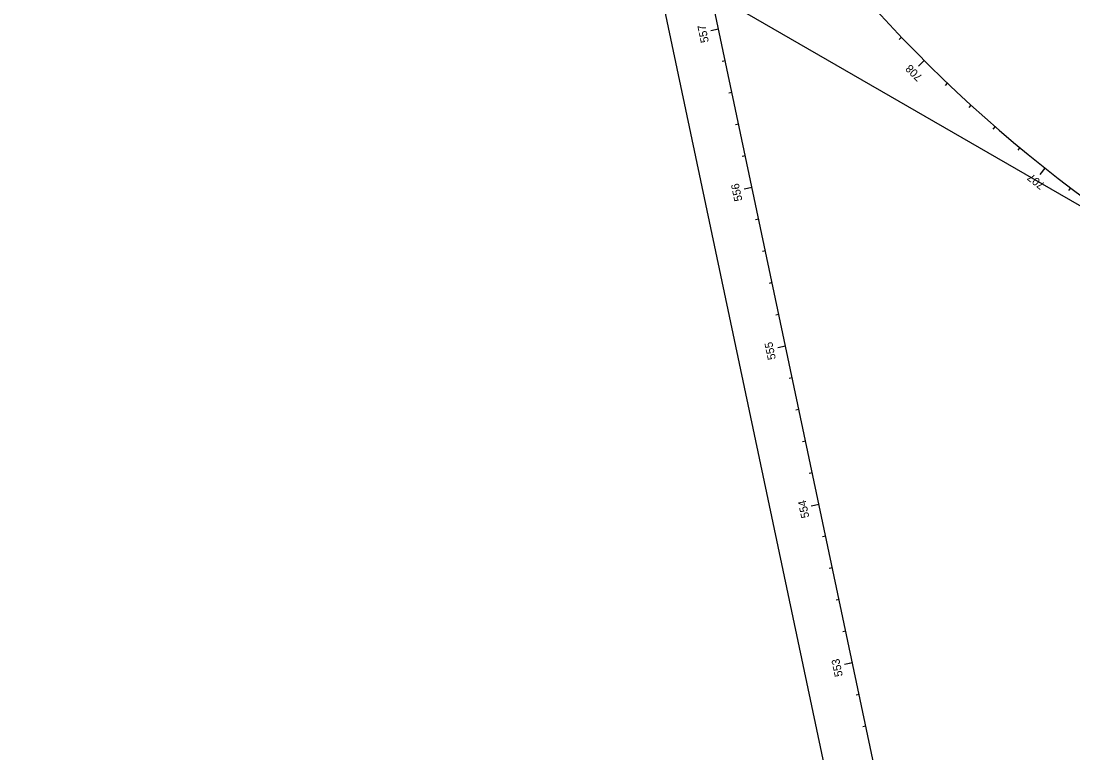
# Model space of a CAD drawing. Extents: x 2003883 to 2007688, y 399149 to 412300.
# Drawn here: x 2005600 to 2006250, y 402640 to 403092 of the extents above; entities that cross this region are included whole.
import ezdxf

# ---------------------------------------------------------------- set-up
doc = ezdxf.new("R2010")
doc.units = 0
for name, color, linetype in [('BaselineSurvey', 7, 'Continuous'), ('CLConst_dp', 7, 'Continuous'), ('ConstLines', 7, 'Continuous'), ('Default', 7, 'Continuous'), ('TextAlgnStation100', 7, 'Continuous'), ('TextAlgnStation500', 7, 'Continuous'), ('TextAlgnTicks100', 7, 'Continuous'), ('TextAlgnTicks1000', 7, 'Continuous'), ('TextAlgnTicks500', 7, 'Continuous')]:
    doc.layers.add(name, color=color, linetype=linetype)

msp = doc.modelspace()

# ---------------------------------------------------------------- linework, layer by layer
at = {"layer": 'BaselineSurvey'}
msp.add_line((2006223.92, 402174.38), (2005094.48, 407516.05), dxfattribs=at)
at = {"layer": 'CLConst_dp'}
msp.add_arc((2006780.04, 403691.29), 881, 190.93889, 239.99111, dxfattribs=at)
at = {"layer": 'ConstLines'}
for p, q in [((2006194.57, 402168.18), (2005065.13, 407509.84)), ((2006833.64, 402642.95), (2005101.74, 403643.22))]:
    msp.add_line(p, q, dxfattribs=at)
msp.add_arc((2006780.04, 403691.29), 881, 190.93889, 239.99111, dxfattribs=at)
at = {"layer": 'Default'}
msp.add_line((2006223.92, 402174.38), (2005094.48, 407516.05), dxfattribs=at)
at = {"layer": 'TextAlgnTicks100'}
for p, q in [((2006031.01, 403086.76), (2006026.12, 403085.72)), ((2006143.95, 403081.74), (2006142.5, 403080.36)), ((2006035.15, 403067.19), (2006033.19, 403066.78)), ((2006157.95, 403067.46), (2006154.42, 403063.92)), ((2006039.29, 403047.62), (2006037.33, 403047.21)), ((2006172.27, 403053.5), (2006170.89, 403052.05)), ((2006186.9, 403039.87), (2006185.56, 403038.39)), ((2006043.42, 403028.05), (2006041.47, 403027.64)), ((2006201.84, 403026.57), (2006200.53, 403025.06)), ((2006047.56, 403008.49), (2006045.6, 403008.07)), ((2006217.08, 403013.62), (2006215.8, 403012.08)), ((2006232.61, 403001.01), (2006229.5, 402997.1)), ((2006051.7, 402988.92), (2006046.81, 402987.89)), ((2006248.42, 402988.77), (2006247.21, 402987.17)), ((2006055.84, 402969.35), (2006053.88, 402968.94)), ((2006059.97, 402949.79), (2006058.02, 402949.37)), ((2006064.11, 402930.22), (2006062.15, 402929.8)), ((2006068.25, 402910.65), (2006066.29, 402910.24)), ((2006072.38, 402891.08), (2006067.49, 402890.05)), ((2006076.52, 402871.52), (2006074.57, 402871.1)), ((2006080.66, 402851.95), (2006078.7, 402851.53)), ((2006084.8, 402832.38), (2006082.84, 402831.97)), ((2006088.93, 402812.81), (2006086.98, 402812.4)), ((2006093.07, 402793.25), (2006088.18, 402792.21)), ((2006097.21, 402773.68), (2006095.25, 402773.26)), ((2006101.35, 402754.11), (2006099.39, 402753.7)), ((2006105.48, 402734.54), (2006103.53, 402734.13)), ((2006109.62, 402714.98), (2006107.66, 402714.56)), ((2006113.76, 402695.41), (2006108.87, 402694.37)), ((2006117.9, 402675.84), (2006115.94, 402675.43)), ((2006122.03, 402656.27), (2006120.08, 402655.86))]:
    msp.add_line(p, q, dxfattribs=at)
at = {"layer": 'TextAlgnTicks1000'}
for p, q in [((2006157.95, 403067.46), (2006156.54, 403066.04)), ((2006051.7, 402988.92), (2006049.74, 402988.51)), ((2006093.07, 402793.25), (2006091.11, 402792.83))]:
    msp.add_line(p, q, dxfattribs=at)
at = {"layer": 'TextAlgnTicks500'}
for p, q in [((2006031.01, 403086.76), (2006029.05, 403086.34)), ((2006157.95, 403067.46), (2006156.54, 403066.04)), ((2006232.61, 403001.01), (2006231.37, 402999.45)), ((2006051.7, 402988.92), (2006049.74, 402988.51)), ((2006072.38, 402891.08), (2006067.49, 402890.05)), ((2006093.07, 402793.25), (2006091.11, 402792.83)), ((2006113.76, 402695.41), (2006111.8, 402695))]:
    msp.add_line(p, q, dxfattribs=at)

# ---------------------------------------------------------------- texts
at = {"layer": 'TextAlgnStation100'}
for s, rotation, p in [('557', 101.93882, (2006025.01, 403078.9)), ('708', 135.08022, (2006157.29, 403057.53)), ('707', 141.58372, (2006233, 402991.13)), ('556', 101.93882, (2006045.71, 402981)), ('555', 101.93882, (2006066.4, 402883.13)), ('554', 101.93882, (2006087.07, 402785.37)), ('553', 101.93882, (2006107.78, 402687.44))]:
    msp.add_text(s, height=4.98, rotation=rotation, dxfattribs=at).set_placement(p)
at = {"layer": 'TextAlgnStation500'}
msp.add_text('555', height=4.98, rotation=101.93882, dxfattribs=at).set_placement((2006066.4, 402883.13))

doc.saveas('drawing.dxf')
